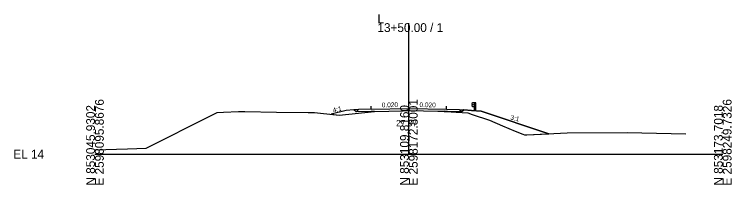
# Model space of a CAD drawing. Extents: x -26 to 1203, y -10 to 9526.
# Drawn here: x -25.7 to 202.8, y 3490.3 to 3544.4 of the extents above; entities that cross this region are included whole.
import ezdxf

# ---------------------------------------------------------------- set-up
doc = ezdxf.new("R2010")
doc.units = 0
for name, color, linetype in [('Default', 7, 'Continuous'), ('Exist Cross Section Cell', 7, 'Continuous'), ('Exist XS Center Line Elevation Label', 7, 'Continuous'), ('Exist XS Ground Line', 7, 'Continuous'), ('Prop XS Earthwork Shape', 7, 'Continuous'), ('Prop XS EOT Tick Mark', 7, 'Continuous'), ('Prop XS Finish Grade', 7, 'Continuous'), ('Prop XS Finish Grade Earthwork', 7, 'Continuous'), ('Prop XS Finish Grade Paved Shoulder', 7, 'Continuous'), ('Prop XS Finish Grade Pavement', 7, 'Continuous'), ('Prop XS Guardrail', 7, 'Continuous'), ('Prop XS Pvmt Edge Slope', 7, 'Continuous'), ('Prop XS SE Text', 7, 'Continuous'), ('Prop XS Side Slope Text', 7, 'Continuous'), ('Prop XS Subgrade Earthwork', 7, 'Continuous')]:
    doc.layers.add(name, color=color, linetype=linetype)

msp = doc.modelspace()

# ---------------------------------------------------------------- linework, layer by layer
at = {"layer": 'Default'}
msp.add_line((100, 3507.6), (100, 3507.6), dxfattribs=at)
at = {"layer": 'Exist Cross Section Cell'}
for p, q in [((100, 3500), (100, 3541.61)), ((0, 3500), (100, 3500)), ((100, 3500), (200, 3500))]:
    msp.add_line(p, q, dxfattribs=at)
at = {"layer": 'Exist XS Ground Line'}
for p, q in [((37.03, 3512.3), (38.92, 3513.25)), ((38.92, 3513.25), (40.92, 3513.34)), ((40.92, 3513.34), (45.74, 3513.56)), ((45.74, 3513.56), (47.74, 3513.53)), ((47.74, 3513.53), (57.84, 3513.37)), ((57.84, 3513.37), (67.93, 3513.23)), ((67.93, 3513.23), (69.93, 3513.2)), ((69.93, 3513.2), (71.84, 3513.06)), ((71.84, 3513.06), (77.81, 3512.42)), ((77.81, 3512.42), (89.01, 3513.51)), ((89.01, 3513.51), (98.2, 3513.81)), ((98.2, 3513.81), (100.05, 3513.87)), ((100.05, 3513.87), (109.27, 3513.69)), ((109.27, 3513.69), (111.23, 3513.65)), ((111.23, 3513.65), (112.3, 3513.57)), ((112.3, 3513.57), (115.07, 3513.34)), ((115.07, 3513.34), (118.75, 3513.07)), ((118.75, 3513.07), (120.18, 3512.62)), ((120.18, 3512.62), (125.69, 3510.82)), ((16.26, 3501.92), (37.03, 3512.3)), ((125.69, 3510.82), (129.87, 3508.97)), ((129.87, 3508.97), (133.9, 3507.29)), ((133.9, 3507.29), (136.33, 3506.29)), ((136.33, 3506.29), (136.8, 3506.09)), ((136.8, 3506.09), (137.57, 3506.1)), ((137.57, 3506.1), (150.42, 3506.76)), ((150.42, 3506.76), (169.6, 3506.89)), ((169.6, 3506.89), (188.23, 3506.41)), ((0, 3501.36), (10.39, 3501.72)), ((10.39, 3501.72), (16.26, 3501.92))]:
    msp.add_line(p, q, dxfattribs=at)
at = {"layer": 'Prop XS Earthwork Shape'}
for points in [[(88, 3513.5), (83.19, 3513.4), (82.5, 3514.09), (80, 3513.89), (75.24, 3512.7), (77.81, 3512.42), (89.01, 3513.51), (89.01, 3513.52)], [(112, 3513.5), (113.51, 3513.47), (112.3, 3513.57), (111.23, 3513.65), (111.23, 3513.51)], [(113.51, 3513.47), (115.07, 3513.34), (118.75, 3513.07), (120.18, 3512.62), (125.69, 3510.82), (129.87, 3508.97), (133.9, 3507.29), (136.33, 3506.29), (136.8, 3506.09), (137.57, 3506.1), (144.58, 3506.46), (123.01, 3513.65), (120, 3513.89), (117.5, 3514.09), (116.81, 3513.4)]]:
    msp.add_lwpolyline(points, close=True, dxfattribs=at)
at = {"layer": 'Prop XS EOT Tick Mark'}
for p, q in [((88, 3514.29), (88, 3515.29)), ((112, 3514.29), (112, 3515.29))]:
    msp.add_line(p, q, dxfattribs=at)
at = {"layer": 'Prop XS Finish Grade'}
for p, q in [((84, 3514.21), (82.5, 3514.09)), ((116, 3514.21), (117.5, 3514.09))]:
    msp.add_line(p, q, dxfattribs=at)
at = {"layer": 'Prop XS Finish Grade Earthwork'}
for p, q in [((80, 3513.89), (75.24, 3512.7)), ((82.5, 3514.09), (80, 3513.89)), ((117.5, 3514.09), (120, 3513.89)), ((120, 3513.89), (123.01, 3513.65)), ((123.01, 3513.65), (144.58, 3506.46))]:
    msp.add_line(p, q, dxfattribs=at)
at = {"layer": 'Prop XS Finish Grade Paved Shoulder'}
for p, q in [((88, 3514.29), (84, 3514.21)), ((112, 3514.29), (116, 3514.21))]:
    msp.add_line(p, q, dxfattribs=at)
at = {"layer": 'Prop XS Finish Grade Pavement'}
for p, q in [((88, 3514.29), (100, 3514.53)), ((100, 3514.53), (112, 3514.29))]:
    msp.add_line(p, q, dxfattribs=at)
at = {"layer": 'Prop XS Guardrail'}
for p, q in [((120.04, 3516.08), (120.01, 3516.02)), ((120.01, 3516.02), (120.04, 3515.96)), ((120.04, 3515.47), (120.01, 3515.41)), ((120.01, 3515.41), (120.04, 3515.35)), ((120.33, 3516.28), (120.04, 3516.08)), ((120.04, 3515.96), (120.33, 3515.76)), ((120.33, 3515.67), (120.04, 3515.47)), ((120.04, 3515.35), (120.33, 3515.15)), ((120.83, 3516.28), (120.33, 3516.28)), ((120.33, 3515.76), (120.33, 3515.67)), ((120.33, 3515.15), (120.83, 3515.15)), ((121.33, 3516.28), (120.83, 3516.28)), ((120.83, 3516.28), (120.83, 3513.78)), ((121.33, 3513.78), (121.33, 3516.28))]:
    msp.add_line(p, q, dxfattribs=at)
at = {"layer": 'Prop XS Pvmt Edge Slope'}
for p, q in [((84, 3514.21), (83.19, 3513.4)), ((116, 3514.21), (116.81, 3513.4))]:
    msp.add_line(p, q, dxfattribs=at)
at = {"layer": 'Prop XS Subgrade Earthwork'}
for p, q in [((83.19, 3513.4), (82.5, 3514.09)), ((88, 3513.5), (83.19, 3513.4)), ((89.01, 3513.52), (88, 3513.5)), ((89.01, 3513.52), (89.01, 3513.51)), ((111.23, 3513.51), (111.23, 3513.65)), ((111.23, 3513.51), (112, 3513.5)), ((112, 3513.5), (116.81, 3513.4)), ((116.81, 3513.4), (117.5, 3514.09))]:
    msp.add_line(p, q, dxfattribs=at)

# ---------------------------------------------------------------- texts
at = {"layer": 'Exist Cross Section Cell'}
for s, p in [('L', (90, 3541.61)), ('13+50.00 / 1', (90, 3538.81)), ('EL 14', (-26, 3498.6))]:
    msp.add_text(s, height=2.8, dxfattribs=at).set_placement(p)
for s, p in [('E 2598095.8676', (2.8, 3490)), ('E 2598172.8001', (102.8, 3490)), ('E 2598249.7326', (202.8, 3490)), ('N 853045.9302', (0, 3490)), ('N 853109.8160', (100, 3490)), ('N 853173.7018', (200, 3490))]:
    msp.add_text(s, height=2.8, rotation=90, dxfattribs=at).set_placement(p)
at = {"layer": 'Exist XS Center Line Elevation Label'}
msp.add_text('27.87', height=2, dxfattribs=at).set_placement((95.93, 3508.87))
at = {"layer": 'Prop XS SE Text'}
for rotation, p in [(1.1458, (91.38, 3514.86)), (358.8542, (103.38, 3514.96))]:
    msp.add_text('0.020', height=1.5, rotation=rotation, dxfattribs=at).set_placement(p)
at = {"layer": 'Prop XS Side Slope Text'}
for s, rotation, p in [('4:1', 13.2903, (75.93, 3513.17)), ('3:1', 345.9638, (132.22, 3511.02))]:
    msp.add_text(s, height=1.5, rotation=rotation, dxfattribs=at).set_placement(p)

doc.saveas('drawing.dxf')
